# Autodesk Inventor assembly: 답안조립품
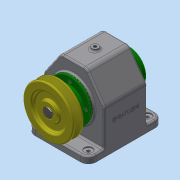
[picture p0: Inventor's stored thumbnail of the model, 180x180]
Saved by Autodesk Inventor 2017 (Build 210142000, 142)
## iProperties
Part Number: 답안조립품
Material: 일반
Document SubType Name: Assembly
Designer: MRC
Author: MRC
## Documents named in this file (15)
- C:\Users\MRC\Desktop\721206V1014\답안조립품.iam
- C:\Users\MRC\Desktop\721206V1014\본체.ipt
- C:\Users\MRC\Desktop\721206V1014\축.ipt
- C:\Users\MRC\Desktop\721206V1014\앞커버.ipt
- C:\Users\MRC\Desktop\721206V1014\뒤커버.ipt
- C:\Users\MRC\Desktop\721206V1014\키 - 6 x 6 x 22.ipt
- C:\Users\MRC\Desktop\721206V1014\스퍼기어.ipt
- C:\Users\MRC\Desktop\721206V1014\칼라.ipt
- C:\Users\MRC\Desktop\721206V1014\베어링 6203.ipt
- C:\Users\MRC\Desktop\721206V1014\오일 실 17 x 32 x 8.ipt
- C:\Users\MRC\Desktop\721206V1014\볼트 M3 x 8.ipt
- C:\Users\MRC\Desktop\721206V1014\볼트 M3 x 10.ipt
- C:\Users\MRC\Desktop\721206V1014\키 - 5 x 5 x 18.ipt
- C:\Users\MRC\Desktop\721206V1014\V-벨트풀리.ipt
- C:\Users\MRC\Desktop\721206V1014\멈춤나사 - M4x10.ipt
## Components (9 placed, 3 different names)
1. ISO 4762 M3 x 8:1
2. ISO 4762 M3 x 8:2
3. ISO 4762 M3 x 8:3
4. ISO 4762 M3 x 8:4
5. ISO 4762 M3 x 10:1
6. ISO 4762 M3 x 10:2
7. ISO 4762 M3 x 10:3
8. ISO 4762 M3 x 10:4
9. V-벨트풀리:1
